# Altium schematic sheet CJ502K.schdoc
size 127 x 101 mm
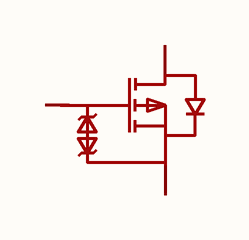
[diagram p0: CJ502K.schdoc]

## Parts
Q?  cj502k  [SOT-23-3_L2.9-W1.3-P1.90-LS2.4-BR]  (value not drawn)

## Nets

Not connected (* = marked no-connect by the designer): Q? 1(G) 2(S) 3(D)

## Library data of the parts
Q? = cj502k: 数量:1个P沟道;漏源电压(Vdss):50V;连续漏极电流(Id):180mA;导通电阻(RDS(on)):8Ω@10V;耗散功率(Pd):420mW;阈值电压(Vgs(th)):2V;; Manufacturer: CJ(江苏长电/长晶); AddInBom: yes; ModelId: c62791f0466c4ae2a892c056b845b0ca; ModelName: SOT-23-3P_L2.9-W1.3-H1.0-LS2.4-P0.95; ModelTransform: 98.425,114.173,0,180,0,0,0.0005,-0.0005,0; Number: 1个P沟道; Drain to Source Voltage: 50V; Current - Continuous Drain(Id): 180mA; RDS(on): 8Ω@10V; Pd - Power Dissipation: 420mW; Gate Threshold Voltage (Vgs(th)): 2V; Input Capacitance(Ciss): 30pF; Reverse Transfer Capacitance (Crss@Vds): 5pF; Type: P沟道; Output Capacitance(Coss): 10pF; Vgs: ±20V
